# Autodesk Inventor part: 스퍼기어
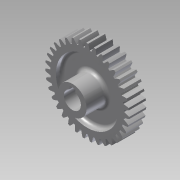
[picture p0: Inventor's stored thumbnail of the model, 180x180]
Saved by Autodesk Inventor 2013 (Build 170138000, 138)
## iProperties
Created: 2013-08
Part Number: 스퍼기어
Material: 강
Document SubType Name: Modeling
Designer: 한국산업디자인학원
Categories: <?xml version="1.0" encoding="UTF-16"?> <MemberInstance><Categories><FamilyTemplate><FamilyTemplateParameter ValueType="xs:double" Id="1" ObjectReferenceKey="da
Density: 1 g/cm^3
CustomPartVersion: 1
Author: 한국산업디자인학원
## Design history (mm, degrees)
sketch "Sketch1"
  geometry: C1 r 37 at (0, 0)
  constraints: 1 centre point
  dimensions: "d0" = 74 diameter of C1 (= da_da)
extrude "Extrusion1" new body sketch "Sketch1" distance "d1" = 15 (= da_b); taper "d2" = 0 deg
workplane "Work Plane2"
feature "피치 지름" dims "d4" = 10, "d5" = 0
workplane "Work Plane8"
workplane "Work Plane9"
feature "스퍼 기어" dims "da_b" = 15, "da_d" = 70, "da_aw" = 70, "da_da" = 74, "da_df" = 65, "da_dw" = 70, angle "da_beta" = 0 deg, "da_lefttooth" = 0, "da_righttooth" = 0
sketch "스케치3"
  geometry: L1 (0.729, 15)-(-0.729, 15) reference; L2 (0, 0)-(0, 15); L3 (-12.5, 0)-(-12.5, 5); L4 (-12.5, 5)-(-27.5, 5); L5 (-27.5, 5)-(-27.5, 0); L6 (-27.5, 0)-(-12.5, 0); L7 (-27.5, 10)-(-12.5, 10); L8 (-12.5, 10)-(-12.5, 15); L9 (-12.5, 15)-(-27.5, 15); L10 (-27.5, 10)-(-27.5, 15)
  constraints: 18 end point, 5 parallel, 3 perpendicular, 2 equal length, 2 horizontal alignment, 1 collinear, 1 midpoint
  dimensions: "d49" = 5 distance between parallel lines of L4 L6; "d51" = 55 diameter of L5 L2; "d52" = 25 diameter of L3 L2
revolve "회전1" sketch "스케치3" stored, may be unused: angle "d53" = 90 deg
sketch "스케치4"
  geometry: C1 r 12.5 at (0, 0) reference; C2 r 12.5 at (0, 0)
  constraints: 1 centre point, 1 coincident, 1 concentric
extrude "돌출2" join sketch "스케치4" distance "d54" = 3; taper "d55" = 0 deg
sketch "스케치5"
  geometry: C1 r 12.5 at (0, 0) reference; C2 r 12.5 at (0, 0)
  constraints: 1 centre point, 1 coincident, 1 concentric
extrude "돌출3" join sketch "스케치5" distance "d56" = 13; taper "d57" = 0 deg
sketch "스케치6"
  geometry: L1 (-2.5, 9.8)-(2.5, 9.8); L2 (-2.5, 9.8)-(-2.5, 7.071); L3 (2.5, 9.8)-(2.5, 7.071); C1 r 12.5 at (0, 0) reference; A1 r 7.5 centre (0, 0) between (-2.5, 7.071) and (2.5, 7.071); 2 further points
  constraints: 6 end point, 3 point on circle, 2 vertical alignment, 1 centre point, 1 coincident, 1 horizontal, 1 midpoint, 1 parallel, 1 perpendicular
  dimensions: "d58" = 15 diameter of A1; "d59" = 5 distance of L1.start L1.end; "d60" = 17.3 distance from line of point (0, -7.5) L1
extrude "돌출4" cut sketch "스케치6" stored distance "d61" = 13; taper "d62" = 0 deg
fillet "모깎기1" dims "d63" = 3
fillet "모깎기2" dims "d64" = 3
body "Solid1"
sketch "Sketch2"
  geometry: C1 r 37 at (0, 0) reference; C2 r 35 at (0, 0)
  constraints: 1 centre point, 1 coincident
  dimensions: "d3" = 70 diameter of C2 (= da_dw)
body "Srf1"
other parameters: "d17" = 0, "d34" = 0.8976 (computed from da_z), "d39" = 0, "d41" = 0, "d47" = 0, "d48" = 0
